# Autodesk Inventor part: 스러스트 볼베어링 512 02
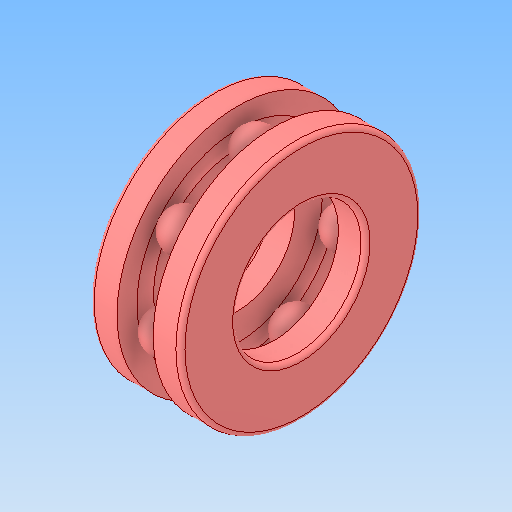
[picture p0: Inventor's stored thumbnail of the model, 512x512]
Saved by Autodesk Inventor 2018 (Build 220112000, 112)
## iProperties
Created: 2024-09
Part Number: 스러스트 볼베어링 512 02
Material: 강철, 연강
Description: 롤링 베어링 - 플랫 뒷면이 있는 스러스트 볼 베어링
Document SubType Name: Modeling
Designer: home
Density: 7.85 g/cm^3
Appearance: 기본값
Author: jhkim
Sending System: Autodesk Inventor 2025
Preprocessor: ST-DEVELOPER v20
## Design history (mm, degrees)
feature "Solid1"
feature "Solid1:1"
feature "Solid1:2"
feature "Solid1:3"
feature "Solid1:4"
feature "Solid1:5"
feature "Solid1:6"
feature "Solid1:7"
feature "Solid1:8"
node "솔리드1"
node "솔리드2"
node "솔리드3"
node "솔리드4"
node "솔리드5"
node "솔리드6"
node "솔리드7"
node "솔리드8"
node "솔리드9"
